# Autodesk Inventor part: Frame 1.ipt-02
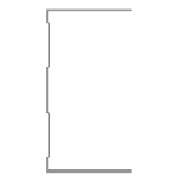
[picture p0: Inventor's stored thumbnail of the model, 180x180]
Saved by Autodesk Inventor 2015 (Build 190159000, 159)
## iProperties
IsCustomPart: 1
Created: 2015-04
Part Number: Frame 1.ipt-02
Material: Aluminum 6061
Description: Kévin Novo
Document SubType Name: Modeling
Standard: Kevin
Designer: suporte
Standards Organization: Kevin
Language: en-US
Size Designation: (Unnamed 2)
Categories: <MemberInstance><Categories><Category DisplayName="Structural Shapes" InternalName="089c4875-fa83-4c05-b084-43b9cc11f5ed" Mnemonic="GRDR"><CategoryParameter Dis
Density: 2.7 g/cm^3
Appearance: Aluminum - Flat
_CCFamilyMember: 2
_CCFamilyDisplayName: Kévin - Kévin Novo
_FrameMemberDoc: Frame Member File
_Version: 15.0.0
_GetPNFromCC: 1
G_W: 50,000 mm
G_H: 75,000 mm
G_L: 2100,000 mm
+45DCE913-32A9-4594-AFB7-6C305E62F3E2+CUTDETAIL1: Notch
Author: suporte
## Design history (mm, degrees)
node "Start Plane"
node "End Plane"
sketch "Sketch"
  geometry: L1 (24.7, 37.5)-(24.7, 36.9); L2 (24.7, 36.9)-(-24.7, 36.9); L3 (-24.7, -36.9)-(24.7, -36.9); L4 (24.7, -36.9)-(24.7, -37.5); L5 (24.7, -37.5)-(-25.3, -37.5); L6 (-25.3, 37.5)-(24.7, 37.5); L7 (-24.7, 36.9)-(-24.7, 31.9); L8 (-24.7, 31.9)-(-23.3, 30.5); L9 (-23.3, 30.5)-(-23.3, 10.934); L10 (-23.3, 10.934)-(-24.7, 9.534); L11 (-24.7, 9.534)-(-24.7, -9.534); L12 (-24.7, -9.534)-(-23.3, -10.934); L13 (-23.3, -10.934)-(-23.3, -30.5); L14 (-23.3, -30.5)-(-24.7, -31.9); L15 (-24.7, -31.9)-(-24.7, -36.9); L16 (-25.3, -37.5)-(-25.3, -31.651); L17 (-25.3, -31.651)-(-23.9, -30.251); L18 (-23.9, -30.251)-(-23.9, -11.183); L19 (-23.9, -11.183)-(-25.3, -9.783); L20 (-25.3, -9.783)-(-25.3, 9.783); L21 (-25.3, 9.783)-(-23.9, 11.183); L22 (-23.9, 11.183)-(-23.9, 30.251); L23 (-23.9, 30.251)-(-25.3, 31.651); L24 (-25.3, 31.651)-(-25.3, 37.5); L25 (-25.3, 0)-(30.37, 0); 3 further points
  constraints: 50 end point, 10 point on line, 9 parallel, 5 perpendicular, 4 equal length, 3 midpoint, 3 vertical, 2 vertical alignment, 1 collinear, 1 horizontal, 1 horizontal alignment
  dimensions: "d3" = 0.6 distance of L1.start L1.end (= d6); "d5" = 75 distance between parallel lines of L5 L6; "d6" = 0.6 distance between parallel lines of L24 L7 (= d8); "d7" = 0.6 distance between parallel lines of L8 L23 (= d8); "d8" = 0.6 distance between parallel lines of L22 L9 (= d12); "Espessura" = 0.6 distance between parallel lines of L17 L14; "d10" = 0.6 distance between parallel lines of L13 L18 (= Espessura); "d11" = 0.6 distance between parallel lines of L12 L19 (= Espessura); "d12" = 0.6 distance between parallel lines of L21 L10 (= d11); "d13" = 5 distance of L2.end L7.end; "d15" = 135 deg angle of L9 L8; "d16" = 2 distance between parallel lines of L24 L9; "d17" = 50 distance of L6.start L1.start
extrude "Body" join sketch "Sketch" stored distance "d24" = 0.13; taper "d25" = 0 deg
node "Driven Length"
  sketch "Sketch10"
    geometry: L1 (0, 0)-(10, 0) reference
    constraints: 2 end point, 1 horizontal
  workplane "Work Plane7"
  sketch "Sketch11"
    geometry: L1 (-2, 0)-(12, 0) reference; L2 (-2, 2100)-(12, 2100) reference
    dimensions: "d27" = 2100 distance between parallel lines of L1 L2 (derived)
workplane "Work Plane8"
workplane "Work Plane9"
workplane "Work Plane10"
sketch "Sketch12"
  geometry: L1 (24.7, 37.5)-(24.7, 36.9); L2 (24.7, 36.9)-(-24.7, 36.9); L3 (-24.7, 36.9)-(-24.7, 31.9); L4 (-24.7, 31.9)-(-23.3, 30.5); L5 (-23.3, 30.5)-(-23.3, 10.934); L6 (-23.3, 10.934)-(-24.7, 9.534); L7 (-24.7, 9.534)-(-24.7, -9.534); L8 (-24.7, -9.534)-(-23.3, -10.934); L9 (-23.3, -10.934)-(-23.3, -30.5); L10 (-23.3, -30.5)-(-24.7, -31.9); L11 (-24.7, -31.9)-(-24.7, -36.9); L12 (-24.7, -36.9)-(24.7, -36.9); L13 (24.7, -36.9)-(24.7, -37.5); L14 (24.7, -37.5)-(-25.3, -37.5); L15 (-25.3, -37.5)-(-25.3, -31.651); L16 (-25.3, -31.651)-(-23.9, -30.251); L17 (-23.9, -30.251)-(-23.9, -11.183); L18 (-23.9, -11.183)-(-25.3, -9.783); L19 (-25.3, -9.783)-(-25.3, 9.783); L20 (-25.3, 9.783)-(-23.9, 11.183); L21 (-23.9, 11.183)-(-23.9, 30.251); L22 (-23.9, 30.251)-(-25.3, 31.651); L23 (-25.3, 31.651)-(-25.3, 37.5); L24 (-25.3, 37.5)-(24.7, 37.5)
  constraints: 48 end point, 10 point on line
extrude "Extrusion3" cut sketch "Sketch12" stored distance "d36" = 0.13; taper "d37" = 0 deg
body "Solid1"
other parameters: "G_OFFSET_START" = 0 [user parameter; used in 1 equation term], "G_OFFSET_END" = 0 [user parameter; used in 1 equation term], "d22" = 0 (computed from G_OFFSET_START), "G_L" = 2100 (= d27) [user parameter], "d34" = 90 deg
